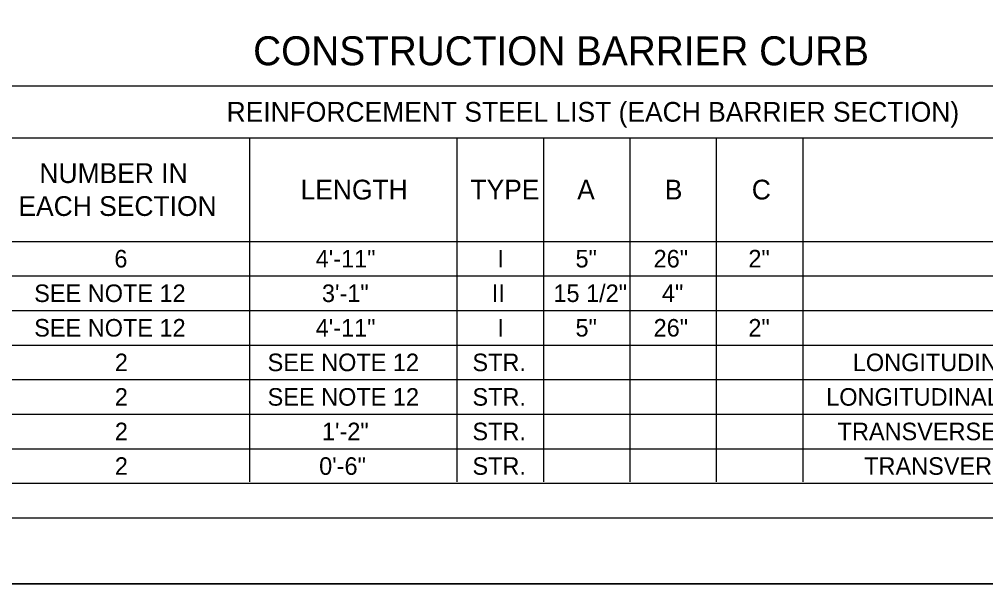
# Model space of a CAD drawing. Extents: x 499866 to 500993, y 499985 to 500645.
# Drawn here: x 500238.9 to 500459, y 499985 to 500113.6 of the extents above; entities that cross this region are included whole.
import ezdxf

# ---------------------------------------------------------------- set-up
doc = ezdxf.new("R2010")
doc.units = 0
for name, color, linetype in [('1', 7, 'Continuous'), ('41', 7, 'Continuous'), ('5', 7, 'Continuous')]:
    doc.layers.add(name, color=color, linetype=linetype)

msp = doc.modelspace()

# ---------------------------------------------------------------- linework, layer by layer
at = {"layer": '1'}
for p, q in [((500000, 500000), (500990, 500000)), ((499944.83, 499985), (500993, 499985))]:
    msp.add_line(p, q, dxfattribs=at)
at = {"layer": '41'}
msp.add_lwpolyline([(499944.83, 500645), (500993, 500645), (500993, 499985), (499944.83, 499985)], close=True, dxfattribs=at)
at = {"layer": '5'}
for p, q in [((500185.04, 500098.43), (500555.12, 500098.43)), ((500185.04, 500086.61), (500555.12, 500086.61)), ((500291.34, 500086.61), (500291.34, 500008.2)), ((500338.58, 500086.61), (500338.58, 500008.2)), ((500358.27, 500086.61), (500358.27, 500008.2)), ((500377.95, 500086.61), (500377.95, 500008.2)), ((500397.64, 500086.61), (500397.64, 500008.2)), ((500417.32, 500086.61), (500417.32, 500008.2)), ((500185.04, 500062.99), (500555.12, 500062.99)), ((500185.04, 500055.12), (500555.12, 500055.12)), ((500185.04, 500047.24), (500555.12, 500047.24)), ((500185.04, 500039.37), (500555.12, 500039.37)), ((500185.04, 500031.5), (500555.12, 500031.5)), ((500185.04, 500023.62), (500555.12, 500023.62)), ((500185.04, 500015.75), (500555.12, 500015.75)), ((500185.04, 500007.87), (500555.12, 500007.87))]:
    msp.add_line(p, q, dxfattribs=at)

# ---------------------------------------------------------------- texts
for s, height, p in [('CONSTRUCTION BARRIER CURB', 6.6001, (500292.17, 500103.13)), ('REINFORCEMENT STEEL LIST (EACH BARRIER SECTION)', 4.5, (500286.12, 500090.27)), ('NUMBER IN', 4.5, (500243.49, 500076.3)), ('LENGTH', 4.5, (500302.96, 500072.55)), ('TYPE', 4.5, (500341.66, 500072.55)), ('A', 4.5, (500365.96, 500072.55)), ('B', 4.5, (500385.92, 500072.55)), ('C', 4.5, (500405.73, 500072.55)), ('EACH SECTION', 4.5, (500238.71, 500068.8)), ('6', 4, (500260.56, 500057.06)), ('4\'-11"', 4, (500306.41, 500057.06)), ('I', 4, (500347.8, 500057.06)), ('5"', 4, (500365.58, 500057.06)), ('26"', 4, (500383.37, 500057.06)), ('2"', 4, (500404.95, 500057.06)), ('SEE NOTE 12', 4, (500242.31, 500049.18)), ('3\'-1"', 4, (500307.83, 500049.18)), ('II', 4, (500346.52, 500049.18)), ('15 1/2"', 4, (500360.55, 500049.18)), ('4"', 4, (500385.26, 500049.18)), ('SEE NOTE 12', 4, (500242.31, 500041.31)), ('4\'-11"', 4, (500306.41, 500041.31)), ('I', 4, (500347.8, 500041.31)), ('5"', 4, (500365.58, 500041.31)), ('26"', 4, (500383.37, 500041.31)), ('2"', 4, (500404.95, 500041.31)), ('2', 4, (500260.67, 500033.43)), ('SEE NOTE 12', 4, (500295.46, 500033.43)), ('STR.', 4, (500342.11, 500033.43)), ('LONGITUDINAL (TOP) NORMAL SECTION', 4, (500428.74, 500033.43)), ('2', 4, (500260.67, 500025.56)), ('SEE NOTE 12', 4, (500295.46, 500025.56)), ('STR.', 4, (500342.11, 500025.56)), ('LONGITUDINAL (BOTTOM) NORMAL SECTION', 4, (500422.68, 500025.56)), ('TRANSVERSE (BOTTOM) NORMAL SECTION', 4, (500425.28, 500017.69)), ('2', 4, (500260.67, 500017.69)), ('1\'-2"', 4, (500307.83, 500017.69)), ('STR.', 4, (500342.11, 500017.69)), ('2', 4, (500260.67, 500009.81)), ('0\'-6"', 4, (500307.2, 500009.81)), ('STR.', 4, (500342.11, 500009.81)), ('TRANSVERSE (TOP) NORMAL SECTION', 4, (500431.33, 500009.81))]:
    msp.add_text(s, height=height, dxfattribs=at).set_placement(p)

doc.saveas('drawing.dxf')
